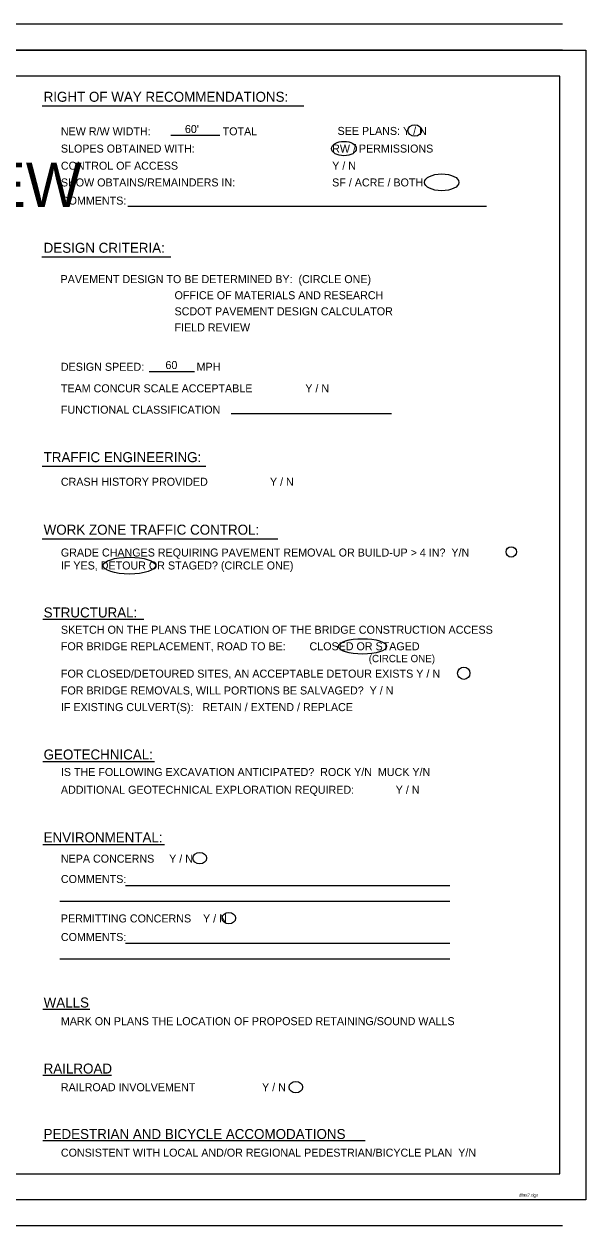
# Model space of a CAD drawing. Extents: x -12279 to -10482, y 3228 to 4378.
# Drawn here: x -11020 to -10482, y 3228 to 4378 of the extents above; entities that cross this region are included whole.
import ezdxf

# ---------------------------------------------------------------- set-up
doc = ezdxf.new("R2010")
doc.units = 0
for name, color, linetype in [('Default', 7, 'Continuous'), ('RD_SHT_Bndy', 7, 'Continuous'), ('RD_SHT_IplotShp', 7, 'Continuous'), ('RD_SHT_Snap', 7, 'Continuous'), ('RD_SHT_TX', 7, 'Continuous')]:
    doc.layers.add(name, color=color, linetype=linetype)

msp = doc.modelspace()

# ---------------------------------------------------------------- linework, layer by layer
at = {"layer": 'RD_SHT_Bndy'}
for p, q in [((-10504.7, 4378), (-12264.7, 4378)), ((-10504.7, 4353), (-12264.7, 4353)), ((-10507.2, 4328), (-12182.2, 4328)), ((-10507.2, 3278), (-10507.2, 4328)), ((-11002.2, 4299.6), (-10751.9, 4299.6)), ((-10879.4, 4271.5), (-10832.5, 4271.5)), ((-10920.4, 4203.6), (-10577.4, 4203.6)), ((-11002.5, 4155.4), (-10989.7, 4155.4)), ((-11002.5, 4155.4), (-10879.4, 4155.4)), ((-10899.9, 4045.6), (-10856.7, 4045.6)), ((-10821.4, 4005.2), (-10668.3, 4005.2)), ((-11002.2, 3954.8), (-10845.7, 3954.8)), ((-11002.2, 3885.4), (-10777, 3885.4)), ((-11001.6, 3808.6), (-10905.1, 3808.6)), ((-11001.6, 3672.3), (-10895, 3672.3)), ((-11001.6, 3593), (-10885.3, 3593)), ((-10922.6, 3553.8), (-10612.4, 3553.8)), ((-10985.5, 3538.8), (-10612.4, 3538.8)), ((-10922.7, 3498.6), (-10612.4, 3498.6)), ((-10985.5, 3483.6), (-10612.4, 3483.6)), ((-11001.6, 3435.4), (-10956.6, 3435.4)), ((-11001.6, 3372.2), (-10935.9, 3372.2)), ((-11001.6, 3309.6), (-10693.5, 3309.6)), ((-12182.2, 3278), (-10507.2, 3278)), ((-10504.7, 3253), (-12264.7, 3253)), ((-10504.7, 3228), (-12264.7, 3228))]:
    msp.add_line(p, q, dxfattribs=at)
at = {"layer": 'RD_SHT_IplotShp'}
msp.add_lwpolyline([(-12278.2, 4353), (-10482.3, 4353), (-10482.3, 3253), (-12278.2, 3253)], close=True, dxfattribs=at)
at = {"layer": 'RD_SHT_Snap'}
msp.add_line((-10482.3, 4353), (-10482.3, 3253), dxfattribs=at)
at = {"layer": 'RD_SHT_TX'}
for centre, radius in [((-10553.7, 3872.9), 4.96), ((-10599.1, 3756.8), 5.91)]:
    msp.add_circle(centre, radius, dxfattribs=at)
for centre, major_axis, ratio in [((-10646, 4276.1), (-6.51, 0), 0.835903), ((-10713.7, 4258.8), (11.8, 0), 0.583497), ((-10620.2, 4226.5), (16.5, 0), 0.487566), ((-10918.9, 3859.8), (25.2, 0), 0.318532), ((-10695.9, 3782.5), (23, 0), 0.32194), ((-10851.6, 3579.9), (-6.51, 0), 0.835903), ((-10823.8, 3522.5), (-6.51, 0), 0.835903), ((-10759.7, 3360.8), (-6.51, 0), 0.835903)]:
    msp.add_ellipse(centre, major_axis=major_axis, ratio=ratio, dxfattribs=at)

# ---------------------------------------------------------------- texts
at = {"layer": 'Default'}
msp.add_text('DESIGN FIELD REVIEW', height=42.444, dxfattribs=at).set_placement((-11598.3, 4203))
at = {"layer": 'RD_SHT_TX'}
for s, height, p in [('RIGHT OF WAY RECOMMENDATIONS:', 9.57, (-11000.9, 4303.6)), ('NEW R/W WIDTH:', 7.656, (-10984.4, 4271.5)), ("60'", 7.66, (-10865.8, 4273.7)), ('TOTAL', 7.66, (-10829.7, 4271.5)), ('SEE PLANS: Y / N', 7.656, (-10719.8, 4271.9)), ('SLOPES OBTAINED WITH:', 7.656, (-10984.4, 4255)), (' RW / PERMISSIONS', 7.656, (-10727.8, 4255)), ('CONTROL OF ACCESS', 7.656, (-10984.4, 4238.6)), (' Y / N', 7.66, (-10727.8, 4238.6)), ('SHOW OBTAINS/REMAINDERS IN:', 7.656, (-10984.4, 4222.6)), (' SF / ACRE / BOTH', 7.656, (-10727.8, 4222.6)), ('COMMENTS:', 7.66, (-10984.4, 4205.2)), ('DESIGN CRITERIA:', 9.57, (-11000.9, 4159.1)), ('PAVEMENT DESIGN TO BE DETERMINED BY:  (CIRCLE ONE)', 7.656, (-10984.7, 4130.1)), ('OFFICE OF MATERIALS AND RESEARCH', 7.656, (-10875.7, 4114.7)), ('SCDOT PAVEMENT DESIGN CALCULATOR', 7.656, (-10875.7, 4099.3)), ('FIELD REVIEW', 7.656, (-10875.7, 4083.9)), ('DESIGN SPEED:', 7.656, (-10984.4, 4046.2)), ('60', 7.66, (-10884.4, 4047.9)), ('MPH', 7.66, (-10854.6, 4046.2)), ('TEAM CONCUR SCALE ACCEPTABLE', 7.656, (-10984.4, 4025.6)), (' Y / N', 7.66, (-10753.5, 4025.6)), ('FUNCTIONAL CLASSIFICATION', 7.656, (-10984.4, 4005.2)), ('TRAFFIC ENGINEERING:', 9.57, (-11000.9, 3958.8)), ('CRASH HISTORY PROVIDED', 7.656, (-10984.4, 3936.2)), (' Y / N', 7.66, (-10787.3, 3936.2)), ('WORK ZONE TRAFFIC CONTROL:', 9.57, (-11000.9, 3889.4)), ('GRADE CHANGES REQUIRING PAVEMENT REMOVAL OR BUILD-UP > 4 IN?  Y/N', 7.656, (-10984.4, 3868.5)), ('IF YES, DETOUR OR STAGED? (CIRCLE ONE)', 7.656, (-10984.4, 3856.1)), ('STRUCTURAL:', 9.57, (-11000.9, 3810.2)), ('SKETCH ON THE PLANS THE LOCATION OF THE BRIDGE CONSTRUCTION ACCESS ', 7.7, (-10984.4, 3794.6)), ('FOR BRIDGE REPLACEMENT, ROAD TO BE:        CLOSED OR STAGED', 7.656, (-10984.4, 3778.8)), ('(CIRCLE ONE)', 7, (-10690, 3767.4)), ('FOR CLOSED/DETOURED SITES, AN ACCEPTABLE DETOUR EXISTS Y / N', 7.7, (-10984.4, 3752.6)), ('FOR BRIDGE REMOVALS, WILL PORTIONS BE SALVAGED?  Y / N', 7.656, (-10984.4, 3736.5)), ('IF EXISTING CULVERT(S):   RETAIN / EXTEND / REPLACE', 7.656, (-10984.4, 3720.6)), ('GEOTECHNICAL:', 9.57, (-11000.9, 3674.3)), ('IS THE FOLLOWING EXCAVATION ANTICIPATED?  ROCK Y/N  MUCK Y/N', 7.656, (-10984.4, 3658.5)), ('ADDITIONAL GEOTECHNICAL EXPLORATION REQUIRED:', 7.656, (-10984.4, 3641.5)), ('Y / N', 7.66, (-10664.2, 3641.5)), ('ENVIRONMENTAL:', 9.57, (-11000.9, 3595)), ('NEPA CONCERNS     Y / N', 7.656, (-10984.4, 3575.6)), ('COMMENTS:', 7.66, (-10984.4, 3556.1)), ('PERMITTING CONCERNS    Y / N', 7.656, (-10984.4, 3518.4)), ('COMMENTS:', 7.66, (-10984.4, 3500.6)), ('WALLS', 9.57, (-11000.9, 3437)), ('MARK ON PLANS THE LOCATION OF PROPOSED RETAINING/SOUND WALLS', 7.656, (-10984.4, 3420.1)), ('RAILROAD', 9.57, (-11000.9, 3373.8)), ('RAILROAD INVOLVEMENT', 7.656, (-10984.4, 3356.9)), ('Y / N', 7.66, (-10792, 3356.9)), ('PEDESTRIAN AND BICYCLE ACCOMODATIONS', 9.57, (-11000.9, 3311.2)), ('CONSISTENT WITH LOCAL AND/OR REGIONAL PEDESTRIAN/BICYCLE PLAN  Y/N', 7.656, (-10984.4, 3294.3)), ('dfrts7.dgn', 3, (-10546.2, 3255.9))]:
    msp.add_text(s, height=height, dxfattribs=at).set_placement(p)

doc.saveas('drawing.dxf')
